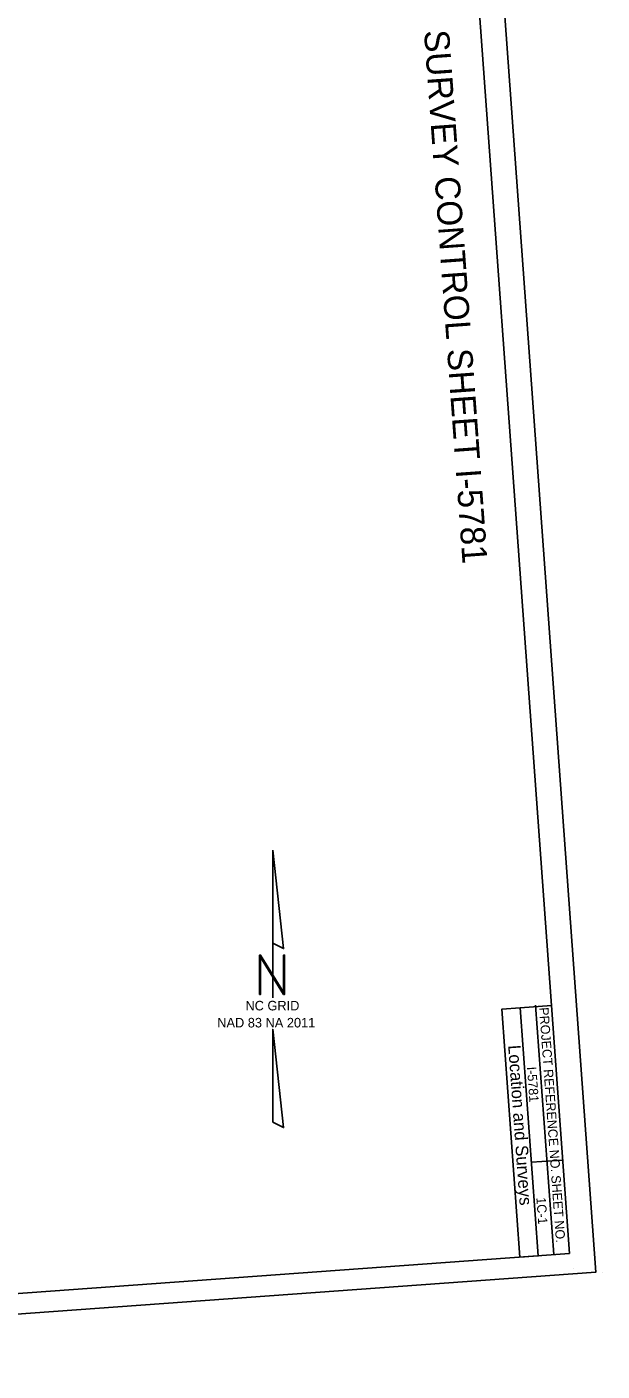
# Model space of a CAD drawing. Extents: x 2130621 to 2131998, y 642516 to 644503.
# Drawn here: x 2131478 to 2131998, y 642516 to 643732 of the extents above; entities that cross this region are included whole.
import ezdxf

# ---------------------------------------------------------------- set-up
doc = ezdxf.new("R2010")
doc.units = 0
for name, color, linetype in [('CTL North Arrow NAD 83 NA 2011 CELL', 7, 'Continuous'), ('CTL Sheet Border CELL', 7, 'Continuous'), ('Sheet Plot Border Outside CELL', 7, 'Continuous')]:
    doc.layers.add(name, color=color, linetype=linetype)

msp = doc.modelspace()

# ---------------------------------------------------------------- linework, layer by layer
at = {"layer": 'CTL North Arrow NAD 83 NA 2011 CELL'}
msp.add_line((2131700.7, 642861.1), (2131700.7, 642861.1), dxfattribs=at)
for points in [[(2131700.5, 642986.8), (2131700.5, 642902.8), (2131710.4, 642897.9)], [(2131688.6, 642856.4), (2131689.6, 642856.4), (2131689.6, 642890), (2131710.4, 642856.4), (2131711.3, 642856.4), (2131711.3, 642892), (2131710.4, 642892), (2131710.4, 642858.4), (2131689.6, 642892), (2131688.6, 642892)], [(2131700.5, 642740.8), (2131710.4, 642735.9), (2131700.5, 642824.8)]]:
    msp.add_lwpolyline(points, close=True, dxfattribs=at)
msp.add_lwpolyline([(2131700.5, 642902.8), (2131700.5, 642853.4)], dxfattribs=at)
at = {"layer": 'CTL Sheet Border CELL'}
for p, q in [((2131952.5, 642846.3), (2131924.3, 642844.2)), ((2131938.3, 642846.5), (2131954.7, 642621)), ((2131962.6, 642706.5), (2131934.4, 642704.5)), ((2131972.7, 642608.1), (2131972.7, 642608.1)), ((2131972.7, 642608.1), (2131972.7, 642608.1)), ((2131998.4, 642604.9), (2131998.4, 642604.9))]:
    msp.add_line(p, q, dxfattribs=at)
for points in [[(2131968.8, 642622), (2131846.3, 644313.2), (2130662.5, 644227.5), (2130785, 642536.2)], [(2131924.3, 642844.2), (2131940.6, 642619.9), (2131924, 642618.7), (2131907.7, 642843)]]:
    msp.add_lwpolyline(points, close=True, dxfattribs=at)
at = {"layer": 'Sheet Plot Border Outside CELL'}
msp.add_lwpolyline([(2130620.6, 644413.7), (2130758.1, 642515.6), (2131992.7, 642605.1), (2131855.2, 644503.1)], close=True, dxfattribs=at)

# ---------------------------------------------------------------- texts
at = {"layer": 'CTL North Arrow NAD 83 NA 2011 CELL'}
for s, p in [('NC GRID', (2131675.9, 642841.9)), ('NAD 83 NA 2011', (2131650.4, 642826.5))]:
    msp.add_text(s, height=8.64, dxfattribs=at).set_placement(p)
at = {"layer": 'CTL Sheet Border CELL'}
for s, height, p in [('SURVEY CONTROL SHEET I-5781', 22.609, (2131837.3, 643728)), ('PROJECT REFERENCE NO.', 8.478, (2131941.4, 642844.4)), ('Location and Surveys', 11.305, (2131913.4, 642810.2)), ('I-5781', 8.48, (2131930.4, 642790.7)), ('SHEET NO.', 8.48, (2131952.3, 642692.5)), ('1C-1', 8.48, (2131938.9, 642672.6))]:
    msp.add_text(s, height=height, rotation=274.1431, dxfattribs=at).set_placement(p)

doc.saveas('drawing.dxf')
